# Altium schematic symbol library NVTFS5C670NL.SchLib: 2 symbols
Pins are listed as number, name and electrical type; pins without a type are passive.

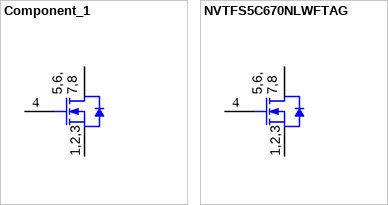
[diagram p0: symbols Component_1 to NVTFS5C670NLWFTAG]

## Component_1
designator U?, comment Used in BOM report  Supplier Part Number 1: NVTFS5C670NLWFTAG-ND
SymbolVersion: use current date i.e. 2008-05-20; SymbolCreator: Use a-id; CompType: Used in some BOM reports.  Useful for finding later.; U/M: EA, IN, or GM
pins: 1 S, 2 S, 3 S, 4 G, 5 D, 6 D, 7 D, 8 D, 9 D

## NVTFS5C670NLWFTAG
designator Q?, comment Used in BOM report  Supplier Part Number 1: NVTFS5C670NLWFTAG-ND  Supplier Part Number 2: 863-NVTFS5C670NLTAG
MOSFET N-CH 60V 16A 70A 8WDFN; SymbolVersion: use current date i.e. 2008-05-20; SymbolCreator: Use a-id; CompType: FET; U/M: EA, IN, or GM
footprint Power_WDFN-8 (SMD, 8-Leads, Body 3.3x3.3mm, Pitch 0.65mm)
pins: 1 S, 2 S, 3 S, 4 G, 5 D, 6 D, 7 D, 8 D, 9 D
